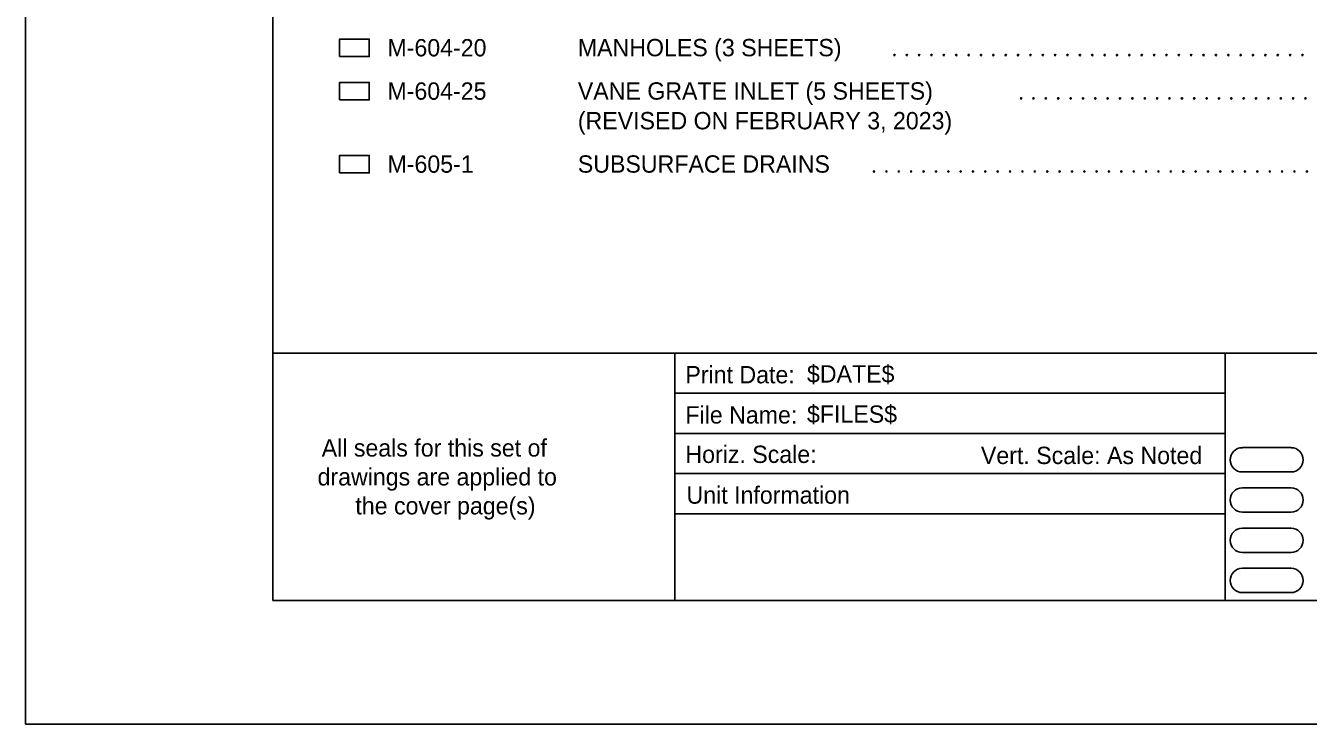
# Model space of a CAD drawing. Extents: x 0 to 1.42, y 0 to 0.92.
# Drawn here: x 0 to 0.4322, y 0 to 0.2353 of the extents above; entities that cross this region are included whole.
import ezdxf

# ---------------------------------------------------------------- set-up
doc = ezdxf.new("R2010")
doc.units = 0
for name, color, linetype in [('DRAFT_Text-Notes', 7, 'Continuous'), ('DRAFT_Text-Titles', 7, 'Continuous'), ('SHEET_Lines', 7, 'Continuous'), ('SHEET_Plot Boundary', 7, 'Continuous'), ('SHEET_Text-Border Info', 7, 'Continuous')]:
    doc.layers.add(name, color=color, linetype=linetype)

msp = doc.modelspace()

# ---------------------------------------------------------------- linework, layer by layer
at = {"layer": 'DRAFT_Text-Notes'}
for centre in [(0.29275, 0.22535), (0.29691, 0.22535), (0.30108, 0.22535), (0.30525, 0.22535), (0.30941, 0.22535), (0.31358, 0.22535), (0.31775, 0.22535), (0.32191, 0.22535), (0.32608, 0.22535), (0.33025, 0.22535), (0.33441, 0.22535), (0.33858, 0.22535), (0.34275, 0.22535), (0.34691, 0.22535), (0.35108, 0.22535), (0.35525, 0.22535), (0.35941, 0.22535), (0.36358, 0.22535), (0.36775, 0.22535), (0.37191, 0.22535), (0.37608, 0.22535), (0.38025, 0.22535), (0.38441, 0.22535), (0.38858, 0.22535), (0.39275, 0.22535), (0.39691, 0.22535), (0.40108, 0.22535), (0.40525, 0.22535), (0.40941, 0.22535), (0.41358, 0.22535), (0.41775, 0.22535), (0.42191, 0.22535), (0.42608, 0.22535), (0.43025, 0.22535), (0.33544, 0.21076), (0.33961, 0.21076), (0.34377, 0.21076), (0.34794, 0.21076), (0.35211, 0.21076), (0.35627, 0.21076), (0.36044, 0.21076), (0.36461, 0.21076), (0.36877, 0.21076), (0.37294, 0.21076), (0.37711, 0.21076), (0.38127, 0.21076), (0.38544, 0.21076), (0.38961, 0.21076), (0.39377, 0.21076), (0.39794, 0.21076), (0.40211, 0.21076), (0.40627, 0.21076), (0.41044, 0.21076), (0.41461, 0.21076), (0.41877, 0.21076), (0.42294, 0.21076), (0.42711, 0.21076), (0.43127, 0.21076), (0.28589, 0.18617), (0.29006, 0.18617), (0.29423, 0.18617), (0.29839, 0.18617), (0.30256, 0.18617), (0.30673, 0.18617), (0.31089, 0.18617), (0.31506, 0.18617), (0.31923, 0.18617), (0.32339, 0.18617), (0.32756, 0.18617), (0.33173, 0.18617), (0.33589, 0.18617), (0.34006, 0.18617), (0.34423, 0.18617), (0.34839, 0.18617), (0.35256, 0.18617), (0.35673, 0.18617), (0.36089, 0.18617), (0.36506, 0.18617), (0.36923, 0.18617), (0.37339, 0.18617), (0.37756, 0.18617), (0.38173, 0.18617), (0.38589, 0.18617), (0.39006, 0.18617), (0.39423, 0.18617), (0.39839, 0.18617), (0.40256, 0.18617), (0.40673, 0.18617), (0.41089, 0.18617), (0.41506, 0.18617), (0.41923, 0.18617), (0.42339, 0.18617), (0.42756, 0.18617), (0.43173, 0.18617)]:
    msp.add_circle(centre, 0.000208, dxfattribs=at)
for centre, start, end in [((0.29275, 0.22535), 0, 180), ((0.29275, 0.22535), 180, 0), ((0.29691, 0.22535), 0, 180), ((0.29691, 0.22535), 180, 0), ((0.30108, 0.22535), 0, 180), ((0.30108, 0.22535), 180, 0), ((0.30525, 0.22535), 0, 180), ((0.30525, 0.22535), 180, 0), ((0.30941, 0.22535), 0, 180), ((0.30941, 0.22535), 180, 0), ((0.31358, 0.22535), 0, 180), ((0.31358, 0.22535), 180, 0), ((0.31775, 0.22535), 0, 180), ((0.31775, 0.22535), 180, 0), ((0.32191, 0.22535), 0, 180), ((0.32191, 0.22535), 180, 0), ((0.32608, 0.22535), 0, 180), ((0.32608, 0.22535), 180, 0), ((0.33025, 0.22535), 0, 180), ((0.33025, 0.22535), 180, 0), ((0.33441, 0.22535), 0, 180), ((0.33441, 0.22535), 180, 0), ((0.33858, 0.22535), 0, 180), ((0.33858, 0.22535), 180, 0), ((0.34275, 0.22535), 0, 180), ((0.34275, 0.22535), 180, 0), ((0.34691, 0.22535), 0, 180), ((0.34691, 0.22535), 180, 0), ((0.35108, 0.22535), 0, 180), ((0.35108, 0.22535), 180, 0), ((0.35525, 0.22535), 0, 180), ((0.35525, 0.22535), 180, 0), ((0.35941, 0.22535), 0, 180), ((0.35941, 0.22535), 180, 0), ((0.36358, 0.22535), 0, 180), ((0.36358, 0.22535), 180, 0), ((0.36775, 0.22535), 0, 180), ((0.36775, 0.22535), 180, 0), ((0.37191, 0.22535), 0, 180), ((0.37191, 0.22535), 180, 0), ((0.37608, 0.22535), 0, 180), ((0.37608, 0.22535), 180, 0), ((0.38025, 0.22535), 0, 180), ((0.38025, 0.22535), 180, 0), ((0.38441, 0.22535), 0, 180), ((0.38441, 0.22535), 180, 0), ((0.38858, 0.22535), 0, 180), ((0.38858, 0.22535), 180, 0), ((0.39275, 0.22535), 0, 180), ((0.39275, 0.22535), 180, 0), ((0.39691, 0.22535), 0, 180), ((0.39691, 0.22535), 180, 0), ((0.40108, 0.22535), 0, 180), ((0.40108, 0.22535), 180, 0), ((0.40525, 0.22535), 0, 180), ((0.40525, 0.22535), 180, 0), ((0.40941, 0.22535), 0, 180), ((0.40941, 0.22535), 180, 0), ((0.41358, 0.22535), 0, 180), ((0.41358, 0.22535), 180, 0), ((0.41775, 0.22535), 0, 180), ((0.41775, 0.22535), 180, 0), ((0.42191, 0.22535), 0, 180), ((0.42191, 0.22535), 180, 0), ((0.42608, 0.22535), 0, 180), ((0.42608, 0.22535), 180, 0), ((0.43025, 0.22535), 0, 180), ((0.43025, 0.22535), 180, 0), ((0.33544, 0.21076), 0, 180), ((0.33544, 0.21076), 180, 0), ((0.33961, 0.21076), 0, 180), ((0.33961, 0.21076), 180, 0), ((0.34377, 0.21076), 0, 180), ((0.34377, 0.21076), 180, 0), ((0.34794, 0.21076), 0, 180), ((0.34794, 0.21076), 180, 0), ((0.35211, 0.21076), 0, 180), ((0.35211, 0.21076), 180, 0), ((0.35627, 0.21076), 0, 180), ((0.35627, 0.21076), 180, 0), ((0.36044, 0.21076), 0, 180), ((0.36044, 0.21076), 180, 0), ((0.36461, 0.21076), 0, 180), ((0.36461, 0.21076), 180, 0), ((0.36877, 0.21076), 0, 180), ((0.36877, 0.21076), 180, 0), ((0.37294, 0.21076), 0, 180), ((0.37294, 0.21076), 180, 0), ((0.37711, 0.21076), 0, 180), ((0.37711, 0.21076), 180, 0), ((0.38127, 0.21076), 0, 180), ((0.38127, 0.21076), 180, 0), ((0.38544, 0.21076), 0, 180), ((0.38544, 0.21076), 180, 0), ((0.38961, 0.21076), 0, 180), ((0.38961, 0.21076), 180, 0), ((0.39377, 0.21076), 0, 180), ((0.39377, 0.21076), 180, 0), ((0.39794, 0.21076), 0, 180), ((0.39794, 0.21076), 180, 0), ((0.40211, 0.21076), 0, 180), ((0.40211, 0.21076), 180, 0), ((0.40627, 0.21076), 0, 180), ((0.40627, 0.21076), 180, 0), ((0.41044, 0.21076), 0, 180), ((0.41044, 0.21076), 180, 0), ((0.41461, 0.21076), 0, 180), ((0.41461, 0.21076), 180, 0), ((0.41877, 0.21076), 0, 180), ((0.41877, 0.21076), 180, 0), ((0.42294, 0.21076), 0, 180), ((0.42294, 0.21076), 180, 0), ((0.42711, 0.21076), 0, 180), ((0.42711, 0.21076), 180, 0), ((0.43127, 0.21076), 0, 180), ((0.43127, 0.21076), 180, 0), ((0.28589, 0.18617), 0, 180), ((0.28589, 0.18617), 180, 0), ((0.29006, 0.18617), 0, 180), ((0.29006, 0.18617), 180, 0), ((0.29423, 0.18617), 0, 180), ((0.29423, 0.18617), 180, 0), ((0.29839, 0.18617), 0, 180), ((0.29839, 0.18617), 180, 0), ((0.30256, 0.18617), 0, 180), ((0.30256, 0.18617), 180, 0), ((0.30673, 0.18617), 0, 180), ((0.30673, 0.18617), 180, 0), ((0.31089, 0.18617), 0, 180), ((0.31089, 0.18617), 180, 0), ((0.31506, 0.18617), 0, 180), ((0.31506, 0.18617), 180, 0), ((0.31923, 0.18617), 0, 180), ((0.31923, 0.18617), 180, 0), ((0.32339, 0.18617), 0, 180), ((0.32339, 0.18617), 180, 0), ((0.32756, 0.18617), 0, 180), ((0.32756, 0.18617), 180, 0), ((0.33173, 0.18617), 0, 180), ((0.33173, 0.18617), 180, 0), ((0.33589, 0.18617), 0, 180), ((0.33589, 0.18617), 180, 0), ((0.34006, 0.18617), 0, 180), ((0.34006, 0.18617), 180, 0), ((0.34423, 0.18617), 0, 180), ((0.34423, 0.18617), 180, 0), ((0.34839, 0.18617), 0, 180), ((0.34839, 0.18617), 180, 0), ((0.35256, 0.18617), 0, 180), ((0.35256, 0.18617), 180, 0), ((0.35673, 0.18617), 0, 180), ((0.35673, 0.18617), 180, 0), ((0.36089, 0.18617), 0, 180), ((0.36089, 0.18617), 180, 0), ((0.36506, 0.18617), 0, 180), ((0.36506, 0.18617), 180, 0), ((0.36923, 0.18617), 0, 180), ((0.36923, 0.18617), 180, 0), ((0.37339, 0.18617), 0, 180), ((0.37339, 0.18617), 180, 0), ((0.37756, 0.18617), 0, 180), ((0.37756, 0.18617), 180, 0), ((0.38173, 0.18617), 0, 180), ((0.38173, 0.18617), 180, 0), ((0.38589, 0.18617), 0, 180), ((0.38589, 0.18617), 180, 0), ((0.39006, 0.18617), 0, 180), ((0.39006, 0.18617), 180, 0), ((0.39423, 0.18617), 0, 180), ((0.39423, 0.18617), 180, 0), ((0.39839, 0.18617), 0, 180), ((0.39839, 0.18617), 180, 0), ((0.40256, 0.18617), 0, 180), ((0.40256, 0.18617), 180, 0), ((0.40673, 0.18617), 0, 180), ((0.40673, 0.18617), 180, 0), ((0.41089, 0.18617), 0, 180), ((0.41089, 0.18617), 180, 0), ((0.41506, 0.18617), 0, 180), ((0.41506, 0.18617), 180, 0), ((0.41923, 0.18617), 0, 180), ((0.41923, 0.18617), 180, 0), ((0.42339, 0.18617), 0, 180), ((0.42339, 0.18617), 180, 0), ((0.42756, 0.18617), 0, 180), ((0.42756, 0.18617), 180, 0), ((0.43173, 0.18617), 0, 180), ((0.43173, 0.18617), 180, 0)]:
    msp.add_arc(centre, 0.000208, start, end, dxfattribs=at)
at = {"layer": 'SHEET_Lines'}
for p, q in [((0.08333, 0.125), (0.08333, 0.04167)), ((0.21875, 0.125), (0.21875, 0.04167)), ((0.40417, 0.04167), (0.40417, 0.125)), ((0.21875, 0.1115), (0.40417, 0.1115)), ((0.21875, 0.09796), (0.40417, 0.09796)), ((0.42637, 0.09316), (0.40999, 0.09316)), ((0.21875, 0.08442), (0.40417, 0.08442)), ((0.42637, 0.08497), (0.40999, 0.08497)), ((0.42637, 0.07962), (0.40999, 0.07962)), ((0.40417, 0.07087), (0.21875, 0.07087)), ((0.42637, 0.07143), (0.40999, 0.07143)), ((0.42637, 0.06607), (0.40999, 0.06607)), ((0.42637, 0.05788), (0.40999, 0.05788)), ((0.42637, 0.05253), (0.40999, 0.05253)), ((0.42637, 0.04434), (0.40999, 0.04434)), ((0.08333, 0.04167), (1.375, 0.04167))]:
    msp.add_line(p, q, dxfattribs=at)
msp.add_lwpolyline([(0.08333, 0.875), (1.375, 0.875), (1.375, 0.125), (0.08333, 0.125)], close=True, dxfattribs=at)
for points in [[(0.10578, 0.22486), (0.11575, 0.22486), (0.11575, 0.23074), (0.10578, 0.23074), (0.10578, 0.22486)], [(0.10578, 0.21027), (0.11575, 0.21027), (0.11575, 0.21615), (0.10578, 0.21615), (0.10578, 0.21027)], [(0.10579, 0.18567), (0.11576, 0.18567), (0.11576, 0.19156), (0.10579, 0.19156), (0.10579, 0.18567)]]:
    msp.add_lwpolyline(points, dxfattribs=at)
for centre, start, end in [((0.40999, 0.08906), 90, 270), ((0.42637, 0.08906), 270, 90), ((0.40999, 0.07552), 90, 270), ((0.42637, 0.07552), 270, 90), ((0.40999, 0.06198), 90, 270), ((0.42637, 0.06198), 270, 90), ((0.40999, 0.04844), 90, 270), ((0.42637, 0.04844), 270, 90)]:
    msp.add_arc(centre, 0.00409, start, end, dxfattribs=at)
at = {"layer": 'SHEET_Plot Boundary'}
msp.add_lwpolyline([(0, 0.91667), (1.41667, 0.91667), (1.41667, 0), (0, 0)], close=True, dxfattribs=at)

# ---------------------------------------------------------------- texts
at = {"layer": 'DRAFT_Text-Notes'}
for s, height, p in [('M-604-20', 0.005833, (0.1219, 0.22491)), ('MANHOLES (3 SHEETS)', 0.0058333, (0.18606, 0.22495)), ('M-604-25', 0.005833, (0.1219, 0.21032)), ('VANE GRATE INLET (5 SHEETS)', 0.0058333, (0.18606, 0.21035)), ('M-605-1', 0.005833, (0.12192, 0.18573)), ('SUBSURFACE DRAINS', 0.0058333, (0.18606, 0.18576))]:
    msp.add_text(s, height=height, dxfattribs=at).set_placement(p)
at = {"layer": 'DRAFT_Text-Titles'}
msp.add_text('(REVISED ON FEBRUARY 3, 2023)', height=0.0058333, dxfattribs=at).set_placement((0.18606, 0.20035))
at = {"layer": 'SHEET_Text-Border Info'}
for s, height, p in [('$DATE$', 0.005833, (0.26327, 0.11509)), ('Print Date:', 0.0058333, (0.22231, 0.11482)), ('File Name:', 0.005833, (0.22231, 0.10128)), ('$FILES$', 0.005833, (0.26327, 0.10155)), ('All seals for this set of', 0.0058333, (0.09976, 0.09016)), ('Horiz. Scale:', 0.0058333, (0.22231, 0.08801)), ('Vert. Scale: As Noted', 0.0058333, (0.32188, 0.08764)), ('drawings are applied to', 0.0058333, (0.09836, 0.08042)), ('Unit Information', 0.0058333, (0.22268, 0.07429)), ('the cover page(s)', 0.0058333, (0.11111, 0.07068))]:
    msp.add_text(s, height=height, dxfattribs=at).set_placement(p)

doc.saveas('drawing.dxf')
